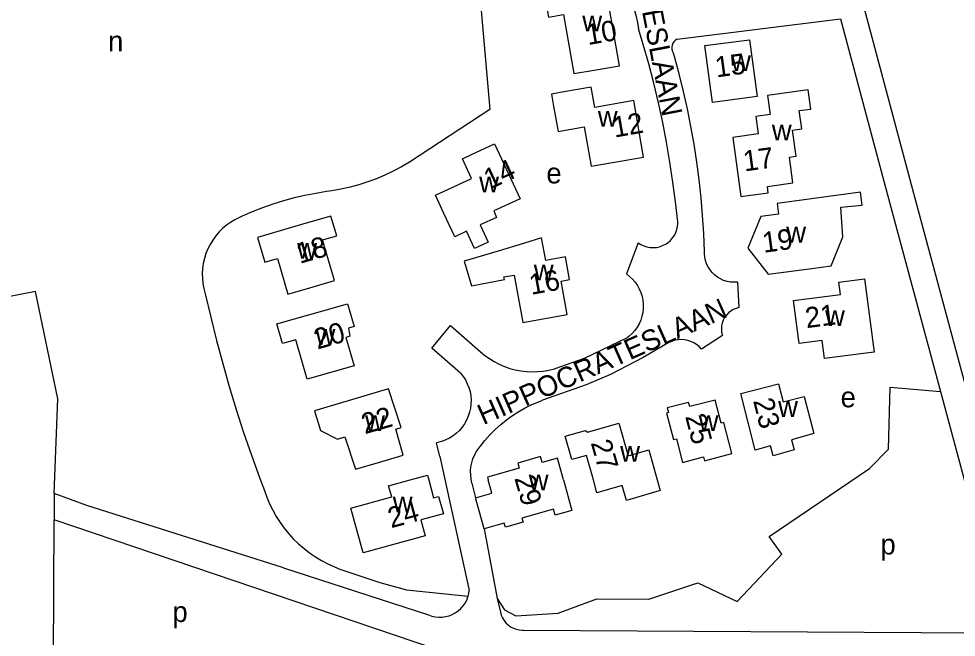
# Model space of a CAD drawing. Extents: x 161093 to 163177, y 379000 to 380904.
# Drawn here: x 162617.8 to 162800.3, y 379969.3 to 380089.8 of the extents above; entities that cross this region are included whole.
import ezdxf

# ---------------------------------------------------------------- set-up
doc = ezdxf.new("R2010")
doc.units = 0
for name, color, linetype in [('BLT_Basislijn', 7, 'Continuous'), ('BLT_Bebouwing', 7, 'Continuous'), ('BLT_Centroide', 7, 'Continuous'), ('BLT_Huisnummer', 7, 'Continuous'), ('BLT_Straatnaam_verkleind', 7, 'Continuous')]:
    doc.layers.add(name, color=color, linetype=linetype)

msp = doc.modelspace()

# ---------------------------------------------------------------- linework, layer by layer
at = {"layer": 'BLT_Basislijn'}
for p, q in [((162707.67, 380093.63), (162709.55, 380072.09)), ((162745.99, 380085.77), (162777.8, 380089.71)), ((162709.55, 380072.09), (162693.87, 380061.86)), ((162738.44, 380046.15), (162736.12, 380040.07)), ((162757.74, 380038.48), (162758.04, 380033.51)), ((162754.81, 380028.08), (162750.73, 380025.46)), ((162699.78, 380004.56), (162699.16, 380007.19)), ((162699.78, 380004.56), (162705.52, 379978.46)), ((162706.05, 379999.35), (162706.75, 379996.49)), ((162624.7, 379997.35), (162624.71, 379992.23)), ((162624.6, 379965.05), (162624.71, 379992.23)), ((162708.43, 379990.45), (162710.99, 379976.87)), ((162669.36, 379982.83), (162697.62, 379973.69)), ((162710.99, 379976.87), (162711.58, 379974.23)), ((162716.06, 379970.72), (162805.49, 379970.18))]:
    msp.add_line(p, q, dxfattribs=at)
for points in [[(162735.21, 380097), (162735.9, 380095.75), (162736.53, 380094.47), (162737.08, 380093.15), (162737.56, 380091.8), (162737.96, 380090.43), (162738.28, 380089.04), (162738.51, 380087.79)], [(162781.9, 380093.73), (162791.32, 380058.47), (162810.03, 379989.05), (162814.92, 379971.78)], [(162777.8, 380089.71), (162786.49, 380057.17), (162797.26, 380017.2)], [(162746.14, 380050.19), (162745.71, 380054.08), (162745.19, 380057.97), (162744.6, 380061.84), (162743.93, 380065.71), (162743.19, 380069.55), (162742.36, 380073.38), (162741.46, 380077.2), (162740.47, 380080.99), (162739.41, 380084.77), (162738.51, 380087.79)], [(162745.99, 380085.77), (162745.67, 380085.56), (162745.39, 380085.3), (162745.17, 380084.98), (162745.02, 380084.62), (162744.95, 380084.25), (162744.96, 380083.86), (162745.04, 380083.49), (162745.21, 380083.14), (162745.27, 380083.03)], [(162751.32, 380044.42), (162751.18, 380047.92), (162750.97, 380051.42), (162750.67, 380054.91), (162750.3, 380058.39), (162749.84, 380061.86), (162749.31, 380065.32), (162748.69, 380068.76), (162748, 380072.2), (162747.23, 380075.61), (162746.39, 380079.01), (162745.46, 380082.38), (162745.27, 380083.03)], [(162693.87, 380061.86), (162692.32, 380060.94), (162690.73, 380060.09), (162689.11, 380059.32), (162687.45, 380058.61), (162685.76, 380057.99), (162684.05, 380057.43), (162682.31, 380056.96), (162680.55, 380056.56), (162678.78, 380056.24), (162677.75, 380056.09)], [(162677.75, 380056.09), (162675.62, 380055.76), (162673.51, 380055.36), (162671.42, 380054.87), (162669.34, 380054.3), (162667.29, 380053.66), (162665.26, 380052.95), (162663.26, 380052.15), (162661.29, 380051.29), (162659.89, 380050.62)], [(162659.89, 380050.62), (162659.05, 380050.11), (162658.24, 380049.54), (162657.49, 380048.91), (162656.79, 380048.22), (162656.15, 380047.47), (162655.57, 380046.67), (162655.06, 380045.83), (162654.62, 380044.95), (162654.25, 380044.03), (162653.96, 380043.09), (162653.74, 380042.13), (162653.6, 380041.16), (162653.54, 380040.17), (162653.57, 380039.19), (162653.67, 380038.21), (162653.85, 380037.24), (162654.13, 380036.21)], [(162738.44, 380046.15), (162738.96, 380045.81), (162739.52, 380045.55), (162740.12, 380045.36), (162740.73, 380045.24), (162741.35, 380045.21), (162741.97, 380045.25), (162742.58, 380045.37), (162743.16, 380045.58), (162743.72, 380045.85), (162744.24, 380046.2), (162744.71, 380046.6), (162745.12, 380047.07), (162745.47, 380047.58), (162745.75, 380048.14), (162745.96, 380048.72), (162746.09, 380049.33), (162746.14, 380049.95), (162746.14, 380050.19)], [(162757.74, 380038.48), (162757.06, 380038.45), (162756.38, 380038.49), (162755.71, 380038.61), (162755.06, 380038.81), (162754.44, 380039.09), (162753.86, 380039.44), (162753.32, 380039.85), (162752.83, 380040.33), (162752.4, 380040.85), (162752.04, 380041.43), (162751.75, 380042.04), (162751.53, 380042.68), (162751.38, 380043.35), (162751.32, 380044.03), (162751.32, 380044.42)], [(162736.12, 380040.07), (162736.74, 380039.6), (162737.3, 380039.06), (162737.81, 380038.47), (162738.26, 380037.83), (162738.64, 380037.15), (162738.94, 380036.43), (162739.17, 380035.69), (162739.33, 380034.93), (162739.4, 380034.15), (162739.4, 380033.37), (162739.31, 380032.59), (162739.15, 380031.83), (162738.9, 380031.09), (162738.59, 380030.38), (162738.2, 380029.7), (162737.75, 380029.07), (162737.23, 380028.48), (162736.65, 380027.96), (162736.35, 380027.71)], [(162624.7, 379997.35), (162625.43, 380015.79), (162621.09, 380036.66), (162594.8, 380031.54)], [(162654.13, 380036.21), (162655.18, 380031.67), (162656.31, 380027.14), (162657.52, 380022.63), (162658.8, 380018.14), (162660.16, 380013.67), (162661.6, 380009.23), (162663.11, 380004.81), (162664.7, 380000.42), (162665.65, 379997.89)], [(162758.04, 380033.51), (162757.47, 380033.36), (162756.94, 380033.14), (162756.44, 380032.84), (162755.98, 380032.48), (162755.58, 380032.05), (162755.24, 380031.58), (162754.97, 380031.07), (162754.78, 380030.52), (162754.65, 380029.95), (162754.61, 380029.37), (162754.65, 380028.79), (162754.77, 380028.22), (162754.81, 380028.08)], [(162703.84, 380020.75), (162698.27, 380025.62), (162701.86, 380030.05), (162707.73, 380024.93)], [(162722.24, 380021.66), (162727.99, 380023.68), (162736.35, 380027.71)], [(162744.41, 380026.71), (162739.37, 380023.83), (162733.03, 380020.51), (162728.28, 380018.49), (162719.79, 380015.47)], [(162750.73, 380025.46), (162750.3, 380025.93), (162749.8, 380026.33), (162749.26, 380026.68), (162748.68, 380026.95), (162748.08, 380027.14), (162747.45, 380027.26), (162746.81, 380027.3), (162746.18, 380027.27), (162745.55, 380027.15), (162744.94, 380026.95), (162744.41, 380026.71)], [(162707.73, 380024.93), (162708.57, 380024.22), (162709.46, 380023.58), (162710.39, 380023), (162711.37, 380022.49), (162712.38, 380022.05), (162713.42, 380021.69), (162714.48, 380021.41), (162715.56, 380021.2), (162716.65, 380021.07), (162717.75, 380021.02), (162718.85, 380021.05), (162719.94, 380021.16), (162721.02, 380021.35), (162722.09, 380021.62), (162722.24, 380021.66)], [(162703.84, 380020.75), (162704.35, 380020.11), (162704.79, 380019.43), (162705.15, 380018.7), (162705.45, 380017.95), (162705.67, 380017.16), (162705.81, 380016.36), (162705.88, 380015.55), (162705.86, 380014.74), (162705.76, 380013.93), (162705.59, 380013.14), (162705.33, 380012.36), (162705.01, 380011.62), (162704.61, 380010.91), (162704.14, 380010.24), (162703.61, 380009.62), (162703.02, 380009.06), (162702.38, 380008.56), (162701.7, 380008.12), (162700.97, 380007.76), (162700.21, 380007.46), (162699.43, 380007.24), (162699.16, 380007.19)], [(162710.99, 379976.87), (162712.38, 379974.65), (162714.59, 379973.49), (162722.85, 379974.01), (162730.34, 379976.85), (162740.52, 379976.75), (162750.04, 379979.92), (162757.72, 379976.33), (162766.36, 379985.54), (162763.89, 379988.95), (162783.43, 380002.22), (162787.17, 380005.96), (162787.46, 380018.06), (162797.26, 380017.2)], [(162797.26, 380017.2), (162805.21, 379987.72), (162809.1, 379973.96)], [(162707.69, 380006.54), (162708.59, 380007.67), (162709.56, 380008.75), (162710.58, 380009.78), (162711.65, 380010.75), (162712.78, 380011.66), (162713.95, 380012.5), (162715.18, 380013.28), (162716.44, 380013.99), (162717.74, 380014.63), (162719.07, 380015.2), (162719.79, 380015.47)], [(162706.05, 379999.35), (162705.88, 380000.13), (162705.8, 380000.92), (162705.79, 380001.72), (162705.86, 380002.51), (162706.01, 380003.29), (162706.24, 380004.05), (162706.55, 380004.78), (162706.93, 380005.48), (162707.37, 380006.14), (162707.69, 380006.54)], [(162669.36, 379982.83), (162631.07, 379995), (162624.7, 379997.35)], [(162665.65, 379997.89), (162666.11, 379996.59), (162666.65, 379995.31), (162667.25, 379994.06), (162667.93, 379992.85), (162668.68, 379991.68), (162669.49, 379990.56), (162670.37, 379989.49), (162671.3, 379988.47), (162672.3, 379987.5), (162673.35, 379986.59), (162674.45, 379985.75), (162675.59, 379984.97), (162676.78, 379984.26), (162678.01, 379983.61), (162679.27, 379983.04), (162680.34, 379982.62)], [(162698.78, 379964.54), (162698.82, 379967.09), (162624.71, 379992.23)], [(162680.34, 379982.62), (162688.11, 379980.03), (162693.3, 379978.59), (162705.31, 379977.36)], [(162705.31, 379977.36), (162705.44, 379977.87), (162705.52, 379978.46)], [(162697.62, 379973.69), (162698.25, 379973.47), (162698.91, 379973.32), (162699.59, 379973.25), (162700.26, 379973.26), (162700.93, 379973.36), (162701.59, 379973.53), (162702.22, 379973.77), (162702.81, 379974.09), (162703.37, 379974.48), (162703.87, 379974.93), (162704.32, 379975.43), (162704.71, 379975.99), (162705.03, 379976.58), (162705.27, 379977.21), (162705.31, 379977.36)], [(162711.58, 379974.23), (162711.74, 379973.66), (162711.98, 379973.11), (162712.29, 379972.6), (162712.66, 379972.14), (162713.1, 379971.73), (162713.58, 379971.38), (162714.11, 379971.1), (162714.67, 379970.9), (162715.25, 379970.77), (162715.85, 379970.72), (162716.06, 379970.72)]]:
    msp.add_lwpolyline(points, dxfattribs=at)
at = {"layer": 'BLT_Bebouwing'}
msp.add_line((162751.41, 380084.52), (162760.11, 380085.68), dxfattribs=at)
for points in [[(162729.84, 380079.76), (162734.76, 380080.61), (162732.73, 380092.38), (162728.25, 380091.61), (162727.63, 380095.22), (162722.7, 380094.37), (162720.31, 380093.96), (162720.98, 380090.09), (162723.89, 380090.6), (162725.88, 380079.07), (162729.84, 380079.76)], [(162760.11, 380085.68), (162761.6, 380074.61), (162752.9, 380073.45), (162751.41, 380084.52)], [(162724.36, 380075.58), (162721.55, 380075.09), (162721.96, 380072.76), (162722.82, 380067.83), (162727.91, 380068.72), (162729.26, 380061.04), (162739.47, 380062.83), (162737.54, 380073.81), (162729.98, 380072.49), (162729.28, 380076.45), (162724.36, 380075.58)], [(162763.62, 380074.8), (162764.13, 380071.11), (162761.3, 380070.72), (162761.77, 380067.32), (162756.82, 380066.64), (162758.4, 380055.12), (162763.75, 380055.86), (162763.58, 380057.1), (162768.54, 380057.78), (162767.85, 380062.79), (162769.18, 380062.98), (162768.48, 380068.05), (162770.28, 380068.29), (162769.79, 380071.86), (162772.05, 380072.17), (162771.54, 380075.89), (162763.62, 380074.8)], [(162705.93, 380063.3), (162710.47, 380065.39), (162715.41, 380054.7), (162710.28, 380052.33), (162710.86, 380051.08), (162707.67, 380049.61), (162709.21, 380046.28), (162706.53, 380045.03), (162704.99, 380048.37), (162702.69, 380047.31), (162700.59, 380051.85), (162698.94, 380055.41), (162705.97, 380058.66), (162704.2, 380062.5), (162705.93, 380063.3)], [(162762.31, 380051.26), (162759.79, 380045.11), (162763.75, 380040), (162772.2, 380041.16), (162775.98, 380041.67), (162778.27, 380047.27), (162777.88, 380053.04), (162782.05, 380053.49), (162781.7, 380056), (162765.46, 380053.78), (162765.74, 380051.73), (162762.31, 380051.26)], [(162674.49, 380037.38), (162679.29, 380038.78), (162676.98, 380046.7), (162679.71, 380047.5), (162678.6, 380051.33), (162673.8, 380049.93), (162664.32, 380047.17), (162665.72, 380042.35), (162668.17, 380043.06), (162670.19, 380036.13), (162674.49, 380037.38)], [(162716.27, 380046.07), (162711.13, 380044.53)], [(162720.41, 380042.71), (162719.62, 380047.07), (162716.27, 380046.07)], [(162711.13, 380044.53), (162704.55, 380042.57), (162705.98, 380037.76), (162712.36, 380038.98), (162712.26, 380039.49), (162714.26, 380039.85), (162715.94, 380030.61), (162724.6, 380032.18), (162723.42, 380038.67), (162725.06, 380038.97), (162724.25, 380043.41), (162720.41, 380042.71)], [(162781.79, 380024.5), (162774.7, 380023.58), (162774.24, 380027.1), (162769.74, 380026.52), (162768.66, 380034.92), (162777.81, 380036.09), (162777.5, 380038.47), (162782.5, 380039.11), (162784.34, 380024.83)], [(162678.3, 380020.81), (162673.94, 380019.56), (162671.73, 380027.26), (162669.18, 380026.52), (162668.08, 380030.33), (162677.02, 380032.9), (162681.83, 380034.28), (162683.1, 380029.85), (162682.02, 380029.54), (162682.29, 380027.93), (162681.52, 380027.71), (162683.11, 380022.19), (162678.3, 380020.81)], [(162784.34, 380024.83), (162781.79, 380024.5)], [(162758.39, 380016.8), (162765.76, 380018.7), (162766.67, 380015.16), (162770.74, 380016.2), (162772.59, 380009), (162768.26, 380007.78), (162768.8, 380005.86), (162764.69, 380004.69), (162764.15, 380006.61), (162761.22, 380005.78), (162758.39, 380016.8)], [(162687.88, 380003.38), (162692.68, 380004.77), (162691.26, 380009.84), (162692.27, 380010.18), (162689.81, 380017.71), (162685.02, 380016.29), (162675.41, 380013.44), (162676.55, 380009.6), (162679.85, 380007.9), (162681.31, 380008.38), (162683.37, 380002.08), (162687.88, 380003.38)], [(162744.07, 380013.99), (162744.31, 380013.09), (162743.92, 380012.99), (162745.27, 380007.82), (162745.86, 380007.98), (162747.05, 380003.39), (162751.12, 380004.45), (162751.32, 380003.7), (162756.67, 380005.09), (162755.09, 380011.17), (162754.58, 380011.04), (162753.41, 380015.53), (162748.46, 380014.24), (162748.24, 380015.07), (162744.07, 380013.99)], [(162729.7, 380000.01), (162728.33, 380004.75), (162725.48, 380003.93), (162724.17, 380008.47), (162728.14, 380009.61), (162728.53, 380009.25), (162734.64, 380011.02), (162736.48, 380004.68), (162740.46, 380005.83), (162742.14, 380000)], [(162723.88, 380000.01), (162722.68, 380004.23), (162719.74, 380003.39), (162719.41, 380004.53), (162714.97, 380003.26), (162715.25, 380002.26), (162709.06, 380000.49), (162709.2, 380000)], [(162694.03, 380000), (162697.38, 380000.92), (162697.63, 380000)], [(162697.63, 380000), (162698.58, 379996.5), (162699.56, 379996.77), (162700.49, 379993.38), (162696.12, 379992.19), (162696.96, 379989.12), (162684.85, 379985.8), (162682.48, 379994.47), (162690.44, 379996.65), (162689.83, 379998.85), (162694.03, 380000)], [(162706.75, 379996.49), (162709.93, 379997.37), (162709.2, 380000)], [(162723.88, 380000.01), (162725.47, 379994), (162722.27, 379993.09), (162721.93, 379994.28), (162715.79, 379992.53), (162716.01, 379991.76), (162712.56, 379990.77), (162712.34, 379991.55), (162711.61, 379991.34), (162708.43, 379990.45)], [(162742.14, 380000), (162742.72, 379997.89), (162736.15, 379995.99), (162735.32, 379998.87), (162730.38, 379997.44), (162729.7, 380000.01)], [(162708.03, 379991.88), (162706.75, 379996.49)], [(162708.43, 379990.45), (162708.03, 379991.88)]]:
    msp.add_lwpolyline(points, dxfattribs=at)

# ---------------------------------------------------------------- texts
at = {"layer": 'BLT_Centroide'}
for s, p in [('w', (162727.53, 380087.27)), ('n', (162635.2, 380083.38)), ('w', (162756.5, 380079.56)), ('w', (162730.55, 380068.75)), ('w', (162764.44, 380066.06)), ('e', (162720.54, 380057.7)), ('w', (162707.45, 380055.94)), ('w', (162767.24, 380046.19)), ('w', (162672.02, 380043.03)), ('w', (162718.09, 380038.81)), ('w', (162774.8, 380029.94)), ('w', (162675.59, 380026.27)), ('e', (162777.83, 380014.11)), ('w', (162765.66, 380012.25)), ('w', (162685.25, 380009.48)), ('w', (162750.19, 380009.47)), ('w', (162734.91, 380003.5)), ('w', (162717.1, 379997.94)), ('w', (162690.63, 379993.66)), ('p', (162785.59, 379985.45)), ('p', (162647.73, 379972.31))]:
    msp.add_text(s, height=4, dxfattribs=at).set_placement(p)
at = {"layer": 'BLT_Huisnummer'}
for s, rotation, p in [('10', 9.7882, (162728.64, 380084.62)), ('15', 7.6464, (162753.64, 380078.32)), ('12', 9.9449, (162733.81, 380066.6)), ('17', 7.8417, (162759.12, 380060.02)), ('14', 24.8006, (162709.52, 380056.47)), ('19', 7.7643, (162762.85, 380044.18)), ('18', 16.2382, (162672.53, 380042.02)), ('16', 10.2897, (162717.58, 380035.99)), ('21', 7.3269, (162771.19, 380029.51)), ('20', 16.0241, (162675.96, 380025.34)), ('23', 284.4123, (162760.77, 380015.4)), ('22', 16.1186, (162685.19, 380008.85)), ('25', 284.5807, (162747.54, 380012.35)), ('27', 286.1241, (162729.15, 380007.21)), ('29', 286.1241, (162714.28, 380000.31)), ('24', 15.3031, (162690.31, 379990.55))]:
    msp.add_text(s, height=4, rotation=rotation, dxfattribs=at).set_placement(p)
at = {"layer": 'BLT_Straatnaam_verkleind'}
for rotation, p in [(280.9639, (162733.21, 380121.87)), (23.9025, (162708.26, 380010.61))]:
    msp.add_text('HIPPOCRATESLAAN', height=4, rotation=rotation, dxfattribs=at).set_placement(p)

doc.saveas('drawing.dxf')
